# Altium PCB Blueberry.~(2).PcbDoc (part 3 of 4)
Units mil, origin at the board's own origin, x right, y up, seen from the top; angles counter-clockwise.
Board outline 2559.06 x 2204.72 mil, 6 copper layers (Top Layer, Mid-Layer 1, Mid-Layer 2, Mid-Layer 3, Mid-Layer 4, Bottom Layer); 211 components, 214 nets, 1171 pads, 598 vias.
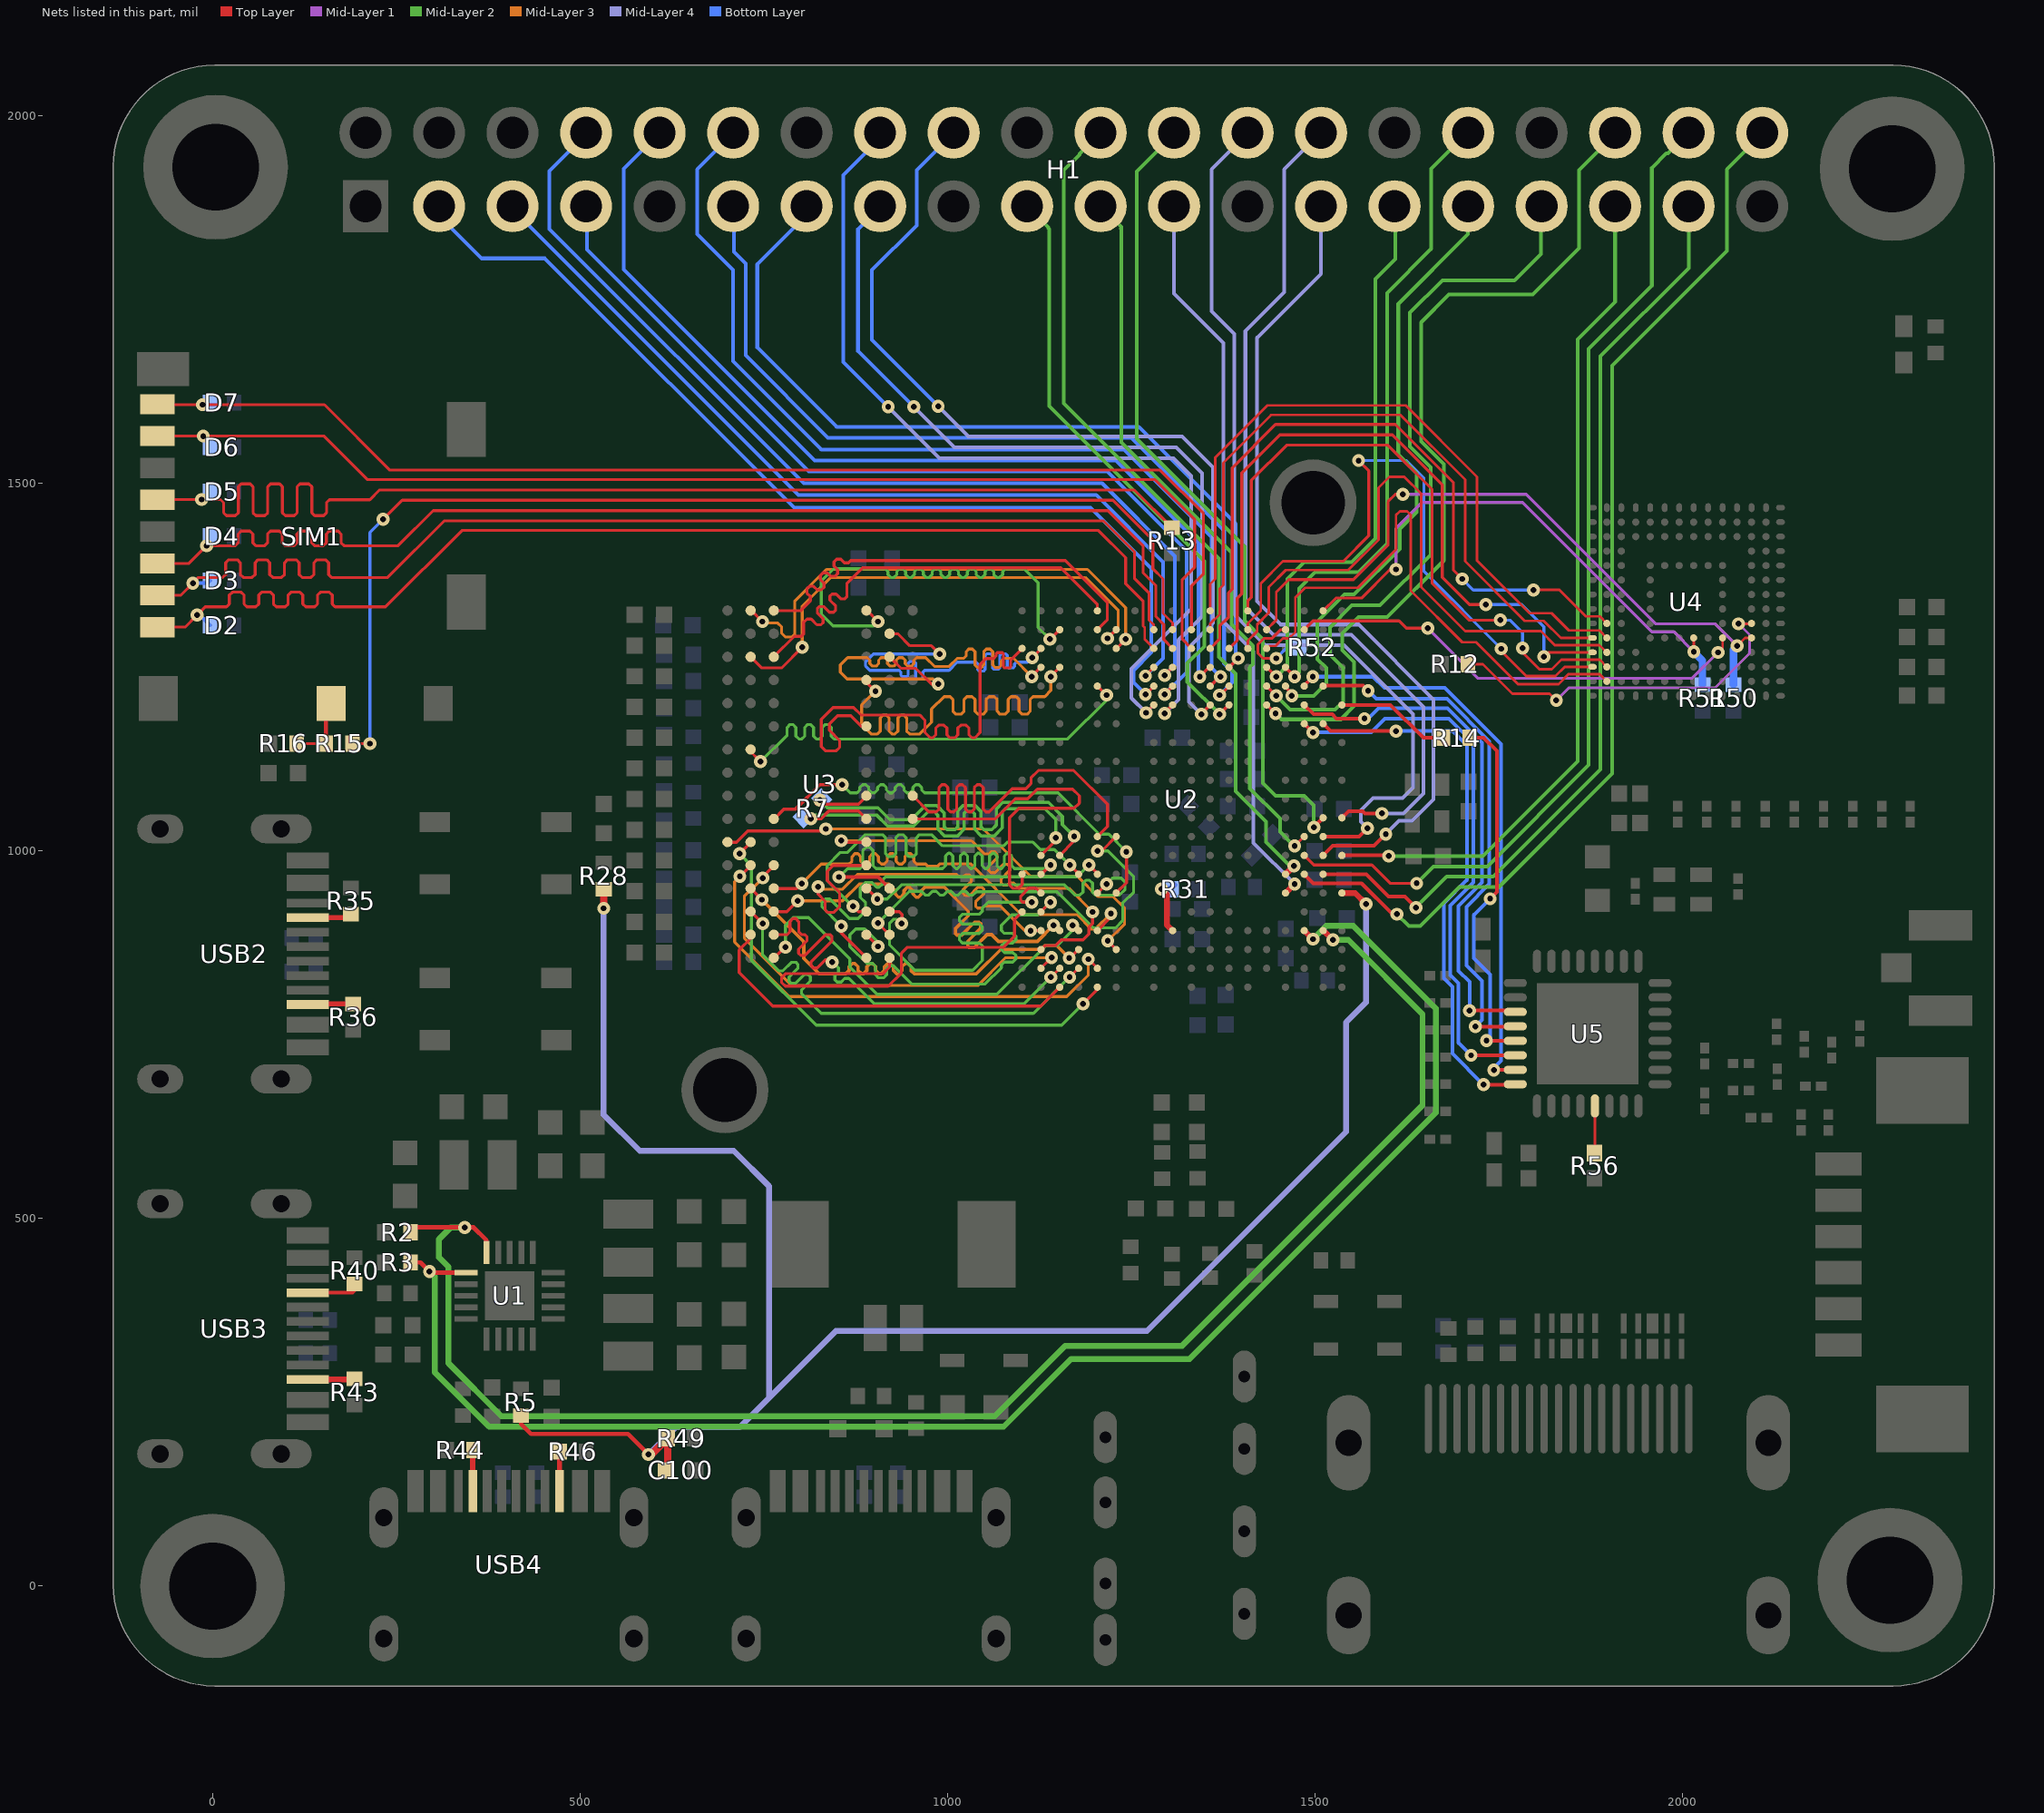
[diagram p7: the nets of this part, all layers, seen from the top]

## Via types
v1: diameter 17.7, hole 7.9, Top Layer to Bottom Layer, 439 vias
v2: diameter 18, hole 8, Top Layer to Bottom Layer, 138 vias
v3: diameter 24, hole 15, Top Layer to Bottom Layer, 19 vias
v4: diameter 24, hole 12, Top Layer to Bottom Layer, 2 vias

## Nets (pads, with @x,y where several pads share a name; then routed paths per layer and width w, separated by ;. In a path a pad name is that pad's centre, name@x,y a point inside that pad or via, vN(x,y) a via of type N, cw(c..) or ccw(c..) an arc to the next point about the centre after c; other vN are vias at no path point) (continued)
NetR14_2: R14.2 U2.A6 | length 156.2
  Top Layer w5: U2.A6@1536.29,1198.63 1602.37,1198.63 1647,1154 R14.2@1674,1154
NetR15_2: R15.2 R16.2 SIM1.11 | length 97.7
  Top Layer w4: R16.2@114,1146 R15.2@154,1146
  Top Layer w6: R15.2@154,1146 154,1193.65 SIM1.11@161.09,1200.74
NetR31_2: R31.2 U2.K18 | length 82.1
  Top Layer w8: v1(1291,948) 1298,941 1298,899.51 U2.K18@1305.97,891.55
  Bottom Layer w8: v1(1291,948) 1301.99,948 R31.2@1308,954
NetR35_2: R35.2 USB2.A5 | length 60.7
  Top Layer w7: USB2.A5@129.3,909.2 183.2,909.2 R35.2@188,914
NetR36_1: R36.1 USB2.B5 | length 62.1
  Top Layer w7: USB2.B5@129.3,791.1 130.2,792 R36.1@191,792
NetR40_2: R40.2 USB3.A5 | length 67.7
  Top Layer w5: USB3.A5@129.3,399.2 190.2,399.2 R40.2@195,404
NetR43_1: R43.1 USB3.B5 | length 64.1
  Top Layer w8: USB3.B5@129.3,281.1 186.09,281.1 186.99,282 R43.1@193,282
NetR44_2: R44.2 USB4.A5 | length 54.4
  Top Layer w7: R44.2@352,183 353.8,181.2 USB4.A5@353.8,129.3
NetR46_1: R46.1 USB4.B5 | length 53.7
  Top Layer w7: USB4.B5@471.9,129.3 472,129.4 R46.1@472,183
NetR52_1: R52.1 U2.D2 | length 122.9
  Top Layer w4: v1(1447,1262) 1429,1262 1422,1269 1422,1281 1430,1289 1441,1289 1452.99,1300.99 U2.D2@1459.52,1300.99
  Bottom Layer w4: v1(1447,1262) 1462,1277 R52.1@1478,1277
NetR56_1: R56.1 U5.29 | length 64.3
  Top Layer w4: R56.1@1880,589.04 1880.5,589.54 U5.29@1880.5,653.11
PH0: H1.23 U2.D16 | length 1007.5
  Top Layer w8: U2.D16@1459.52,942.73 1471.79,955 v1(1472,955)
  Mid-Layer 4 w5: H1.23@1308,1877 1308,1758 1375,1691 1375,1312 1416,1271 1416,1011 v1(1472,955)
PH1: H1.22 U2.D15 | length 1167.4
  Top Layer w8: U2.D15@1459.52,968.32 v1(1471,979.8) v1@1471,980
  Mid-Layer 2 w5: H1.22@1208,1977 1179.19,1948.19 1179.19,1947.19 1158,1926 1158,1609 1369,1398 1369,1264 1392,1241 1392,1081 1433,1040 1433,1012 1465.2,979.8 v1(1471,979.8)
PH2: H1.37 U2.B15 | length 1289.7
  Top Layer w5: U2.B15@1510.7,968.32 1569.68,968.32 1600,938 1622,938 v1(1637,923)
  Mid-Layer 2 w5: v1(1637,923) 1679,965 1742,965 1888,1111 1888,1673 2008,1793 H1.37@2008,1877
PH3: H1.40 U2.C15 | length 1490.6
  Top Layer w5: U2.C15@1485.11,968.32 1497.42,956 1563,956 1605,914 v1(1611,914)
  Mid-Layer 2 w5: v1(1611,914) 1627.35,897.65 1642.65,897.65 1696,951 1750,951 1904,1105 1904,1660 2060,1816 2060,1927 2108,1975 H1.40@2108,1977
PH4: H1.35 U2.A14 | length 1150.6
  Top Layer w5: U2.A14@1536.29,993.91 1599.09,993.91 v1(1600,993)
  Mid-Layer 2 w5: v1(1600,993) 1728,993 1857,1122 1857,1696 1908,1747 H1.35@1908,1877
PH5: H1.27 U2.B14 | length 1186.4
  Top Layer w5: U2.B14@1510.7,993.91 1523.79,1007 1580,1007 v1(1596,1023)
  Mid-Layer 4 w5: H1.27@1508,1877 1508,1785 1421,1698 1421,1340 1453,1308 1559,1308 1661,1206 1661,1070 1632,1041 1614,1041 v1(1596,1023)
PH6: H1.38 U2.C14 | length 1386.8
  Top Layer w4: U2.C14@1485.11,993.91 1498.01,981 1577,981 1602,956 v1(1638,956)
  Mid-Layer 2 w5: v1(1638,956) 1661,979 1734,979 1872,1117 1872,1683 1958,1769 1958,1929 1977.71,1948.71 1979.71,1948.71 H1.38@2008,1977
PH7: H1.24 U2.B12 | length 1107.1
  Top Layer w5: v1(1498,1032) 1498,1032.39 U2.B12@1510.7,1045.09
  Mid-Layer 2 w5: H1.24@1308,1977 1308,1975 1257,1924 1257,1561 1404,1414 1404,1313 1429,1288 1429,1092 1446,1075 1485,1075 1498,1062 v1(1498,1032)
PH8: H1.21 U2.C13 | length 1001.9
  Top Layer w4: v1(1472,1007) 1484.5,1019.5 U2.C13@1485.11,1019.5
  Mid-Layer 2 w5: H1.21@1208,1877 1236,1849 1236,1846 ; 1235.77,1846.23 1236,1846 ; v1(1472,1007) 1471,1007 1452,1026 1452,1044 1411,1085 1411,1250 1415,1254 1415,1279 1386,1308 1386,1406 1236,1556 1236,1846
PH9: H1.28 U2.A12 | length 1230.8
  Top Layer w5: U2.A12@1536.29,1045.09 1545.2,1054 1564.75,1054 1567.72,1051.03 v1(1590.7,1051.03)
  Mid-Layer 4 w5: H1.28@1508,1977 1458,1927 1458,1760 1405,1707 1405,1332 1443,1294 1549,1294 1647,1196 1647,1078 1620.03,1051.03 v1(1590.7,1051.03)
PH10: H1.26 U2.B13 | length 1264.1
  Top Layer w5: U2.B13@1510.7,1019.5 1559.5,1019.5 v1(1571,1031)
  Mid-Layer 4 w5: H1.26@1408,1977 1408,1976 1359,1927 1359,1734 1390,1703 1390,1322 1432,1280 1539,1280 1633,1186 1633,1086 1619,1072 1579,1072 1562,1055 1562,1040 v1(1571,1031)
PI0: H1.18 U2.H6 | length 1238
  Top Layer w4.5: v1(1345,1186) 1345,1186.47 U2.H6@1357.16,1198.63
  Mid-Layer 4 w5: v1(987,1605) 1028,1564 1319,1564 1361,1522 1361,1310 1328,1277 1328,1203 v1(1345,1186)
  Bottom Layer w5: v1(987,1605) 897,1695 897,1790 958,1851 958,1926 1008,1976 H1.18@1008,1977
PI1: H1.32 U2.D4 | length 890.9
  Top Layer w4.5: U2.D4@1459.52,1249.81 1459.52,1249.48 v1(1472,1237)
  Mid-Layer 2 w5: v1(1472,1237) 1478,1243 1478,1357 1500,1379 1559,1379 1598,1418 1598,1759 1658,1819 1658,1928 1707,1977 H1.32@1708,1977
PI2: H1.19 U2.G6 | length 836.6
  Top Layer w4.5: v1(1370,1186) 1382.63,1198.63 U2.G6@1382.75,1198.63
  Mid-Layer 2 w5: H1.19@1108,1877 1136.81,1848.19 1136.81,1847.19 1138,1846 1138,1605 1349,1394 1349,1278 1326,1255 1326,1230 v1(1370,1186)
PI3: H1.29 U2.E4 | length 764
  Top Layer w4.5: U2.E4@1433.93,1249.81 1434.19,1249.81 v1(1447,1237)
  Mid-Layer 2 w5: v1(1447,1237) 1462,1252 1462,1370 1485,1393 1550,1393 1582,1425 1582,1778 1609,1805 1609,1876 H1.29@1608,1877
PI4: H1.11 U2.G5 | length 1214.4
  Top Layer w4.5: v1(1370,1212) 1370.53,1212 U2.G5@1382.75,1224.22
  Bottom Layer w5: H1.11@707,1878 709,1876 709,1815 725,1799 725,1674 837,1562 1250,1562 1376,1436 1376,1255 1387,1244 1387,1229 v1(1370,1212)
PI5: H1.10 U2.H4 | length 1344.7
  Top Layer w4.5: v1(1343,1237) 1355.81,1249.81 U2.H4@1357.16,1249.81
  Bottom Layer w5: H1.10@608,1977 559,1928 559,1791 819,1531 1229,1531 1341,1419 1341,1239 v1(1343,1237)
PI6: H1.12 U2.H5 | length 1315.7
  Top Layer w4.5: U2.H5@1357.16,1224.22 1369.94,1237 v1(1371,1237)
  Bottom Layer w5: H1.12@708,1977 708,1976 659,1927 659,1839 708,1790 708,1666 828,1546 1240,1546 1359,1427 1359,1249 v1(1371,1237)
PI7: H1.13 U2.G4 | length 1171.7
  Top Layer w4.5: U2.G4@1382.75,1249.75 v1(1395,1262)
  Bottom Layer w5: H1.13@808,1877 808,1865 741,1798 741,1685 849,1577 1260,1577 1392,1445 1392,1265 v1(1395,1262)
PI8: H1.36 U2.E6 | length 1190.3
  Top Layer w4.5: U2.E6@1433.93,1198.63 1445.55,1187 v1(1446,1187)
  Mid-Layer 2 w5: v1(1446,1187) 1454,1179 1535,1179 1553,1197 1553,1257 1537,1273 1537,1296 1559,1318 1598,1318 1675,1395 1675,1526 1644,1557 1644,1719 1682,1757 1796,1757 1859,1820 1859,1926 1908,1975 H1.36@1908,1977
PI9: H1.31 U2.D5 | length 837.9
  Top Layer w4.5: U2.D5@1459.52,1224.22 1459.52,1222.73 1468.2,1214.05 v1(1468.2,1211)
  Mid-Layer 2 w5: v1(1468.2,1211) 1498,1211 1515,1228 1515,1249 1503,1261 1503,1312 1540,1349 1553,1349 1615,1411 1615,1438 1638,1461 1638,1514 1613,1539 1613,1744 1708,1839 H1.31@1708,1877
PI10: H1.3 U2.L5 | length 1384.7
  Top Layer w4: v1(1269,1213) 1269.16,1213 U2.L5@1280.38,1224.22
  Bottom Layer w5: H1.3@308,1877 308,1864 366,1806 452,1806 791,1467 1194,1467 1277,1384 1277,1270 1252.65,1245.65 1252.65,1229.35 v1(1269,1213)
PI11: H1.8 U2.K4 | length 1370.3
  Top Layer w4.5: v1(1295,1239) 1295.16,1239 U2.K4@1305.97,1249.81
  Bottom Layer w5: H1.8@508,1977 508,1975 458,1925 458,1846 804,1500 1210,1500 1309,1401 1309,1253 v1(1295,1239)
PI12: H1.7 U2.K5 | length 1268.4
  Top Layer w4.5: v1(1295,1213) 1295,1213.25 U2.K5@1305.97,1224.22
  Bottom Layer w5: H1.7@508,1877 509,1876 509,1818 811,1516 1217,1516 1325,1408 1325,1243 v1(1295,1213)
PI13: H1.33 U2.E5 | length 1025.7
  Top Layer w4.5: U2.E5@1433.93,1224.22 1447,1211.14 v1(1447,1211)
  Mid-Layer 2 w5: v1(1447,1211) 1466,1192 1527,1192 1538,1203 1538,1249 1520,1267 1520,1304 1550,1334 1588,1334 1657,1403 1657,1522 1629,1550 1629,1732 1673,1776 1771,1776 1807,1812 1807,1876 H1.33@1808,1877
PI14: H1.16 U2.L6 | length 1248.7
  Top Layer w4.5: v1(1270,1188) 1270,1188.25 U2.L6@1280.38,1198.63
  Mid-Layer 4 w5: v1(919,1604) 989,1534 1307,1534 1331,1510 1331,1329 1250,1248 1250,1208 v1(1270,1188)
  Bottom Layer w5: H1.16@908,1977 908,1969 858,1919 858,1665 v1(919,1604)
PI15: H1.5 U2.L4 | length 1269.3
  Top Layer w4: v1(1269,1238) 1269,1238.43 U2.L4@1280.38,1249.81
  Bottom Layer w5: H1.5@408,1877 408,1873 797,1484 1202,1484 1293,1393 1293,1262 v1(1269,1238)
PI16: H1.15 U2.K6 | length 1110.5
  Top Layer w4.5: v1(1295,1187) 1295,1187.66 U2.K6@1305.97,1198.63
  Mid-Layer 4 w5: v1(954,1604) 1009,1549 1311,1549 1346,1514 1346,1319 1314,1287 1314,1206 v1(1295,1187)
  Bottom Layer w5: H1.15@908,1877 908,1876 878,1846 878,1680 v1(954,1604)
PMU_SCK: R3.2 U1.6 U2.C18 | length 2170.3
  Top Layer w6: R3.2@269.44,440.28 282.72,440.28 v1(295,428) 296.58,426.42 U1.6@345.02,426.42
  Top Layer w8: U2.C18@1485.11,891.55 1496.65,880 v1(1497,880)
  Mid-Layer 2 w8: v1(295,428) 302,421 302,291 376,217 1076,217 1168,309 1329,309 1664,644 1664,786 1552,898 1515,898 v1(1497,880)
PMU_SDA: R2.2 U1.5 U2.B18 | length 2181.8
  Top Layer w6: R2.2@269.44,481.28 276.16,488 v1(342.84,488) 355,488 372.62,470.38 U1.5@372.62,454.02
  Top Layer w8: U2.B18@1510.7,891.55 1511.45,891.55 v1(1524,879)
  Mid-Layer 2 w8: v1(342.84,488) 324,488 308,472 308,447 321,434 321,303 393,231 1064,231 1160,327 1319,327 1646,654 1646,778 1545,879 v1(1524,879)
RESET: C100.2 R5.1 R28.1 R49.1 U2.A16 | length 2633.3
  Top Layer w6: R5.1@419.44,232.28 419.44,220.56 433,207 565,207 v1(593,179)
  Top Layer w8: U2.A16@1536.29,942.73 1554.27,942.73 v1(1569,928)
  Top Layer w10: v1(532,922) R28.1@532,948 ; v1(593,179) 597,179 R49.1@619,201 619,159.56 C100.2@616.8,157.36
  Mid-Layer 4 w8: v1(532,922) 532,641 581,592 709,592 756.85,544.15 756.85,255.85 ; v1(593,179) 630,216 717,216 756.85,255.85 ; v1(1569,928) 1569,794 1542,767 1542,618 1271,347 848,347 756.85,255.85
SA0: U2.P18 U3.N3 | length 627.4
  Top Layer w4: U3.N3@763.71,948.73 794.46,948.73 v1(801.27,955.53) ; U2.P18@1203.67,891.65 1222,909.98 v1(1222,915)
  Mid-Layer 3 w4: v1(801.27,955.53) 827.73,982 865.74,982 869.74,986 869.74,992.22 873.74,996.22 877.74,996.22 881.74,992.22 881.74,986 885.74,982 889.74,982 893.74,986 893.74,992.22 897.74,996.22 901.74,996.22 905.74,992.22 905.74,986 909.74,982 913.74,982 917.74,986 917.74,992.22 921.74,996.22 925.74,996.22 929.74,992.22 929.74,986 933.74,982 937.74,982 941.74,986 941.74,992.22 945.74,996.22 949.74,996.22 953.74,992.22 953.74,986 957.74,982 970,982 973,979 986,979 989.53,982.53 1030.95,982.53 1100.13,913.35 1175.94,913.35 1195.29,894 1201,894 v1(1222,915)
  other v1: 1222,915
SA1: U2.R15 U3.P7 | length 578.5
  Top Layer w4: v1(871.27,924.53) 878.57,917.23 U3.P7@889.69,917.23 ; v1(1166,981) 1178.08,968.92 U2.R15@1178.08,968.42
  Mid-Layer 2 w4: v1(871.27,924.53) 870.47,924.53 836,959 836,980 854,998 864,998 888,1022 911.36,1022 915.36,1018 915.36,996.22 919.36,992.22 925.36,992.22 929.36,996.22 929.36,1018 933.36,1022 939.36,1022 943.36,1018 943.36,996.22 947.36,992.22 953.36,992.22 957.36,996.22 957.36,1018 961.36,1022 978,1022 993,1007 1076,1007 1081,1012 1116,1012 1126,1002 1145,1002 v1(1166,981)
  other v1: 1166,981
SA2: U2.T18 U3.P3 | length 595.5
  Top Layer w4.5: U3.P3@763.71,917.23 781.23,917.23 v1(796,932) ; v1(1144,899) 1151.35,891.65 U2.T18@1152.49,891.65
  Mid-Layer 3 w4.5: v1(796,932) 856.73,932 879.73,955 919.58,955 928.55,946.03 928.55,941.63 933.05,937.13 936.05,937.13 940.55,941.63 940.55,946.03 945.05,950.53 948.05,950.53 952.55,946.03 952.55,941.63 957.05,937.13 960.05,937.13 964.55,941.63 964.55,946.03 969.05,950.53 995.47,950.53 1027.99,918.01 1027.99,911.65 1010.45,894.11 1010.45,887.74 1012.57,885.62 1018.94,885.62 1036.48,903.16 1042.84,903.16 1044.96,901.04 1044.96,894.68 1027.42,877.13 1027.42,870.77 1029.54,868.65 1035.91,868.65 1053.45,886.19 1059.81,886.19 1069,877 1122,877 v1(1144,899)
SA3: U2.R19 U3.N2 | length 605.8
  Top Layer w4.5: U3.N2@732.21,948.73 v1(747.27,933.67) ; v1@1164.27,854.22 1166.24,854.22 U2.R19@1178.08,866.06
  Mid-Layer 3 w4.5: v1(747.27,933.67) 804.27,876.67 804.27,853.73 825,833 861.47,833 865.97,837.5 865.97,842.5 870.47,847 873.47,847 877.97,842.5 877.97,837.5 882.47,833 885.47,833 889.97,837.5 889.97,842.5 894.47,847 897.47,847 901.97,842.5 901.97,837.5 906.47,833 909.47,833 913.97,837.5 913.97,842.5 918.47,847 921.47,847 925.97,842.5 925.97,837.5 930.47,833 933.47,833 937.97,837.5 937.97,842.5 942.47,847 945.47,847 949.97,842.5 949.97,837.5 954.47,833 1039,833 1072.22,866.22 1127.22,866.22 1132.22,871.22 1148.25,871.22 v1(1165.25,854.22)
  other v1: 1165.25,854.22
SA4: U2.U16 U3.P8 | length 530.8
  Top Layer w4: U3.P8@921.19,917.23 934.07,917.23 937.77,913.53 937.77,901.78 v1(937.2,901.22) ; v1(1114.29,930.22) 1101.58,930.22 1099.27,932.53 1099.27,938.53 1110.27,949.53 1118.52,949.53 1119.12,948.93 1120.79,948.93 U2.U16@1126.9,942.83
  Mid-Layer 2 w4: v1(937.2,901.22) 931.42,907 926,907 921,902 921,872 955.13,837.87 1033.87,837.87 1047,851 1047,870.79 1043,874.79 1019.99,874.79 1015.99,878.79 1015.99,883.79 1019.99,887.79 1043,887.79 1047,891.79 1047,896.79 1043,900.79 1019.99,900.79 1015.99,904.79 1015.99,909.79 1019.99,913.79 1043,913.79 1047,917.79 1047,922 1055.22,930.22 v1(1114.29,930.22)
SA5: U2.R20 U3.P2 | length 633.7
  Top Layer w4: U3.P2@732.21,917.23 v1(748.23,901.22) ; v1(1165.83,828.22) U2.R20@1178.08,840.47
  Mid-Layer 2 w4: v1(748.23,901.22) 748.23,858.77 770.16,836.84 775.82,836.84 787.66,848.68 793.32,848.68 796.15,845.85 796.15,840.19 784.31,828.35 784.31,822.69 787.13,819.87 792.79,819.87 804.63,831.71 810.29,831.71 813.12,828.88 813.12,823.22 801.28,811.38 801.28,805.72 828,779 1116.61,779 v1(1165.83,828.22)
  other v1: 1165.83,828.22
SA6: U2.N13 U3.R8 | length 577.7
  Top Layer w4: v1(905,902) 905,901.58 920.84,885.74 U3.R8@921.19,885.74 ; v1(1204,1000) 1209.66,1000 U2.N13@1229.26,1019.6
  Mid-Layer 2 w4: v1(905,902) 948,945 964.4,945 969.4,940 974.4,940 979.4,945 984.4,945 989.4,940 994.4,940 999.4,945 1004.4,945 1009.4,940 1014.4,940 1019.4,945 1024.4,945 1029.4,940 1034.4,940 1038.97,944.57 1149.14,944.57 1198.25,895.46 1228.46,895.46 1238,905 1238,929 1253,944 1253,965 1218,1000 v1(1204,1000)
SA7: U2.T21 U3.R2 | length 523.5
  Top Layer w4: U3.R2@732.21,885.74 732.21,881.21 716.27,865.27 716.27,834.73 762,789 1126.62,789 U2.T21@1152.49,814.87
SA8: U2.V17 U3.T8 | length 572.8
  Top Layer w4: U3.T8@920.87,854.58 920.87,841.87 912,833 779,833 774,828 774,821 779,816 919,816 937,834 937,861 945,869 1076,869 1091,884 1091,906.89 U2.V17@1101.25,917.14
SA9: U2.T20 U3.R3 | length 628.2
  Top Layer w4: U3.R3@763.37,886.08 781.37,886.08 785.37,890.08 785.37,904 789.37,908 793.37,908 797.37,904 797.37,890.08 801.37,886.08 805.92,886.08 808.59,883.41 808.59,877.75 797.25,866.41 797.25,860.75 800.07,857.93 805.73,857.93 834.07,886.27 839.73,886.27 842.56,883.44 842.56,877.78 814.22,849.44 814.22,843.78 817.05,840.95 822.7,840.95 834.05,852.3 839.7,852.3 v1(843,849) ; v1(1140.27,828.25) U2.T20@1152.49,840.47
  Mid-Layer 2 w4: v1(843,849) 851.31,840.69 851.31,835.03 846.55,830.27 846.55,824.61 849.38,821.78 855.04,821.78 859.8,826.54 865.46,826.54 900,792 1104.02,792 v1(1140.27,828.25)
SA10: U2.U19 U3.L7 | length 596.3
  Top Layer w4: v1(855,1014) 857.28,1011.72 U3.L7@889.69,1011.72 ; U2.U19@1126.9,866.06 1132.06,871.22 1146.27,871.22 1154.27,879.22 1184.27,879.22 1192.16,887.11 1192.16,896.41 1197,901.25 v1(1197,917)
  Mid-Layer 3 w4: v1(855,1014) 1032,1014 1050.05,995.95 1055.71,995.95 1058.54,998.78 1064.19,998.78 1067.02,995.95 1067.02,990.29 1055.71,978.98 1055.71,973.32 1058.54,970.49 1064.19,970.49 1075.51,981.81 1081.17,981.81 1083.99,978.98 1083.99,973.32 1072.68,962.01 1072.68,956.35 1075.51,953.52 1081.17,953.52 1083.99,956.35 1089.65,956.35 1096.78,949.22 1164.78,949.22 v1(1197,917)
  other v1: 1197,917
SA11: U2.U17 U3.R7 | length 570.5
  Top Layer w4: U3.R7@889.69,885.74 v1(905.27,870.16) ; U2.U17@1126.9,917.24 v1(1139.88,930.22)
  Mid-Layer 2 w4: v1(905.27,870.16) 905.27,875.73 887,894 875,894 867,886 867,870 890,847 897.86,847 901.86,843 901.86,831.46 905.86,827.46 912.86,827.46 916.86,831.46 916.86,839.86 921,844 926,844 951,819 1051,819 1073,841 1073,844.89 1077,848.89 1088.67,848.89 1092.67,852.89 1092.67,857.89 1088.67,861.89 1077,861.89 1073,865.89 1073,870.89 1077,874.89 1088.67,874.89 1092.67,878.89 1092.67,883.89 1088.67,887.89 1077,887.89 1073,891.89 1073,899 1087,913 1122.66,913 v1(1139.88,930.22)
  other v1: 1139.88,930.22 1139.88,930.22 1139.88,930.22 1139.88,930.22
SA12: U2.P16 U3.N7 | length 463.6
  Top Layer w4: U3.N7@889.69,948.73 890.07,948.73 v1(904.27,934.53) ; U2.P16@1203.67,942.83 1215.84,955 v1(1216,955)
  Mid-Layer 2 w4: v1(904.27,934.53) 917.53,934.53 937,954 1159,954 1173,940 1180.01,940 1184.01,944 1184.01,956.17 1188.01,960.17 1193.01,960.17 1197.01,956.17 1197.01,944 1201.01,940 1233.73,940 1241.27,947.53 1241.27,957.53 1235.8,963 1224,963 v1(1216,955)
SA13: U2.R18 U3.T3 | length 550.2
  Top Layer w4: U3.T3@763.71,854.24 778.68,869.22 v1(779.27,869.22) ; v1(1170,899) 1177.35,891.65 U2.R18@1178.08,891.65
  Mid-Layer 2 w4: v1(779.27,869.22) 779.27,898.88 789.77,909.38 810.62,909.38 867,853 867,842 904,805 1067,805 1133.22,871.22 1148.95,871.22 1170,892.27 v1(1170,899)
SA14: U2.P15 U3.T7 | length 561.8
  Top Layer w4.5: v1(855.27,897.53) 855.27,888.67 U3.T7@889.69,854.24 ; v1(1192,981) 1203.67,969.33 U2.P15@1203.67,968.42
  Mid-Layer 2 w4: v1(855.27,897.53) 829,923.8 829,930 833.53,934.53 839.47,934.53 866,908 878,908 888.27,918.27 888.27,929.53 881,936.8 881,950 888,957 897,957 903.47,950.53 906.69,950.53 911.19,955.03 911.19,960.5 915.69,965 1176,965 v1(1192,981)
SA15: U2.U18 U3.M7 | length 589
  Top Layer w4: v1(823.62,951.08) 823.62,941.18 833.27,931.53 833.27,919.53 836.27,916.53 845.53,916.53 853,924 853,943 836,960 836,972 844.23,980.23 U3.M7@889.69,980.23 ; v1(1112.84,891.65) U2.U18@1126.9,891.65
  Mid-Layer 3 w4: v1(823.62,951.08) 826.7,948 857,948 877.22,968.22 1011.78,968.22 1015.4,964.6 1021.06,964.6 1023.88,967.43 1029.54,967.43 1032.37,964.6 1032.37,958.94 1021.06,947.63 1021.06,941.97 1023.88,939.14 1029.54,939.14 1040.86,950.46 1046.51,950.46 1049.34,947.63 1049.34,941.97 1038.03,930.66 1038.03,925 1040.86,922.17 1046.51,922.17 1049.34,925 1072,925 1105.35,891.65 v1(1112.84,891.65)
SBA0: U2.P20 U3.M2 | length 676.1
  Top Layer w4: v1(717.27,965.28) U3.M2@732.21,980.23 ; v1(1191.27,852.87) U2.P20@1203.67,840.47
  Mid-Layer 3 w4: v1(717.27,965.28) 710.27,958.28 710.27,876.22 784.48,802 1162,802 1191.27,831.27 v1(1191.27,852.87)
SBA1: U2.U15 U3.N8 | length 599.6
  Top Layer w4.5: v1(852.27,964.53) 905.38,964.53 U3.N8@921.19,948.73 ; U2.U15@1126.84,968.32 1127.32,968.32 v1(1140,981)
  Mid-Layer 2 w4: v1(852.27,964.53) 863.73,976 880.4,976 884.4,980 884.4,1000.4 889,1005 894,1005 898.4,1000.6 898.4,980 902.4,976 993,976 997,980 997,993 1001,997 1003,997 1007,993 1007,980 1011,976 1013,976 1017,980 1017,993 1021,997 1023,997 1027,993 1027,980 1031,976 1033,976 1037,980 1037,993 1041,997 1043,997 1047,993 1047,980 1051,976 1053,976 1057,980 1057,993 1061,997 1063,997 1067,993 1067,980 1071,976 1073,976 1077,980 1077,993 1081,997 1083,997 1087,993 1087,980 1091,976 1135,976 v1(1140,981)
  other v1: 852.27,964.53
SBA2: U2.U20 U3.M3 | length 596.1
  Top Layer w4: v1(748.27,963.22) 748.27,964.78 U3.M3@763.71,980.23 ; U2.U20@1126.9,840.47 v1(1141.27,854.84)
  Mid-Layer 3 w4: v1(748.27,963.22) 723.27,938.22 723.27,881.73 788,817 1041.05,817 1078.89,854.84 v1(1141.27,854.84)
SCAS: U2.N16 U3.K3 | length 650.5
  Top Layer w4.5: U3.K3@763.71,1043.22 777.49,1057 793,1057 826.22,1090.22 v1(856.27,1090.22) ; U2.N16@1229.26,942.83 1243.27,956.84 1243.27,998.73 v1(1243,999)
  Mid-Layer 2 w4: v1(856.27,1090.22) 867.48,1079 876.53,1079 880.53,1083 880.53,1086.18 884.53,1090.18 888.53,1090.18 892.53,1086.18 892.53,1083 896.53,1079 900.53,1079 904.53,1083 904.53,1086.18 908.53,1090.18 912.53,1090.18 916.53,1086.18 916.53,1083 920.53,1079 924.53,1079 928.53,1083 928.53,1086.18 932.53,1090.18 936.53,1090.18 940.53,1086.18 940.53,1083 944.53,1079 948.53,1079 952.53,1083 952.53,1086.18 956.53,1090.18 960.53,1090.18 964.53,1086.18 964.53,1083 968.53,1079 1150,1079 1206,1023 1219,1023 v1(1243,999)
SCK_N: R7.2 U2.U14 U3.K7 | length 602.8
  Top Layer w4: U2.U14@1126.84,993.91 1147,1014.07 v1(1147,1018)
  Top Layer w4.4: v1(814,1044) 828,1044 838.27,1054.27 878.64,1054.27 U3.K7@889.69,1043.22
  Mid-Layer 2 w4.4: v1(814,1044) 819,1049 903.03,1049 917.89,1034.13 954.01,1034.13 973.48,1053.6 981.52,1053.6 986.6,1048.52 986.6,1029.52 995.52,1020.6 1013.48,1020.6 1022.4,1029.52 1022.4,1051.52 1024.48,1053.6 1033.52,1053.6 1036.6,1050.52 1036.6,1029.52 1045.52,1020.6 1063.48,1020.6 1074.4,1031.52 1074.4,1053.52 1078.48,1057.6 1132.4,1057.6 1147,1043 v1(1147,1018)
SCK_P: R7.1 U2.T14 U3.J7 | length 609.4
  Top Layer w4: U2.T14@1152.43,993.91 1172,1013.48 v1(1172,1020)
  Top Layer w4.4: v1(826,1069) 826,1067.56 822.11,1063.67 878.64,1063.67 U3.J7@889.69,1074.71
  Mid-Layer 2 w4.4: v1(826,1069) 836.27,1058.73 905.17,1058.73 921.37,1042.53 950.53,1042.53 970,1062 985,1062 995,1052 995,1033 999,1029 1010,1029 1014,1033 1014,1055 1021,1062 1037,1062 1045,1054 1045,1033 1049,1029 1060,1029 1066,1035 1066,1057 1075,1066 1137,1066 1156,1047 1156,1036 v1(1172,1020)
SCKE0: U2.V15 U3.K9 | length 489.9
  Top Layer w4: U3.K9@949.43,1043.46 1064.46,1043.46 1092,1071 1109,1071 1122,1084 1170,1084 1179,1075 1179,1065 1172,1058 1097,1058 1084,1045 1084,954 1089,949 1095.73,949 1101.31,954.57 U2.V15@1101.31,968.42
SCKE1: U2.P13 U3.J9 | length 566.3
  Top Layer w4: U3.J9@952.37,1075.08 974.44,1053 984.24,1053 988.18,1056.94 988.18,1086.24 992.12,1090.17 996.24,1090.17 1000.18,1086.24 1000.18,1056.94 1004.12,1053 1008.24,1053 1012.18,1056.94 1012.18,1086.24 1016.12,1090.17 1020.24,1090.17 1024.18,1086.24 1024.18,1056.94 1028.12,1053 1032.24,1053 1036.18,1056.94 1036.18,1086.24 1040.12,1090.17 1044.24,1090.17 1048.18,1086.24 1048.18,1056.94 1052.12,1053 1056.4,1053 1087.94,1084.53 1106.27,1084.53 1113.27,1091.53 1113.27,1099.53 1123.27,1109.53 1171.47,1109.53 1217.27,1063.73 1217.27,1033.2 U2.P13@1203.67,1019.6
SCS0: U2.P21 U3.L2 | length 704.3
  Top Layer w4.5: v1(716.71,996.22) U3.L2@732.21,1011.72 ; v1(1184,792) 1203.67,811.67 U2.P21@1203.67,814.82
  Mid-Layer 2 w4.3: v1(716.71,996.22) 732.67,980.26 732.67,851.33 821,763 1155,763 v1(1184,792)
SCS1: U2.N19 U3.L1 | length 662.6
  Top Layer w4: U3.L1@700.72,1011.72 712.46,1011.72 727.95,1027.22 831.22,1027.22 v1(834,1030) ; v1(1217.68,877.63) U2.N19@1229.26,866.06
  Mid-Layer 3 w4: v1(834,1030) 1048,1030 1112.78,965.22 1176.78,965.22 1204,938 1224.8,938 1240.65,922.15 1240.65,900.6 v1(1217.68,877.63)
SD_CLK: R14.1 U5.21 | length 501.8
  Top Layer w5: R14.1@1710,1154 1729,1154 1747,1136 1747,944 v1(1738,935) ; v1(1733,742) 1771.92,742 U5.21@1772.23,741.69
  Bottom Layer w5: v1(1733,742) 1738,747 1738,832.11 1716,854.11 1716,913 v1(1738,935)
SD_CMD: U2.C7 U5.22 | length 767.5
  Top Layer w4: U5.22@1780.24,722 U5.22@1781.23,722
  Top Layer w5: U2.C7@1485.11,1173.04 v1(1497,1161.14) v1@1497,1161 ; v1(1712,722) U5.22@1772.23,722.01
  Bottom Layer w5: v1(1497,1161.14) 1576.14,1161.14 1595,1180 1682.02,1180 1715,1147.02 1715,957.04 1683.5,925.54 1683.5,831.5 1695,820 1695,739 v1(1712,722)
SD_D0: U2.C6 U5.19 | length 721.4
  Top Layer w5: U2.C6@1485.11,1198.63 1497.73,1186 1523,1186 1529,1180 v1(1567,1180) ; v1(1710,783) 1770.29,783 U5.19@1772.23,781.06
  Bottom Layer w5: v1(1567,1180) 1572,1180 1586,1194 1680.04,1194 1727,1147.04 1727,957.02 1695,925.02 1695,837 1710,822 v1(1710,783)
SD_D1: U2.B5 U5.20 | length 725.8
  Top Layer w5: U2.B5@1510.7,1224.22 1511.48,1225 1565,1225 v1(1572,1218) ; v1(1718,761) 1771.85,761 U5.20@1772.23,761.38
  Bottom Layer w5: v1(1572,1218) 1583,1207 1679.06,1207 1737,1149.06 1737,955 1706,924 1706,844 1727,823 1727,770 v1(1718,761)
SD_D2: U2.C5 U5.23 | length 788.4
  Top Layer w5: U2.C5@1485.11,1224.22 1485.11,1224.76 1496.69,1236.34 v1(1496.69,1236.89) ; v1(1743,702) 1771.91,702 U5.23@1772.23,702.32
  Bottom Layer w5: v1(1496.69,1236.89) 1496.8,1237 1579,1237 1594,1222 1676.08,1222 1752.85,1145.23 1752.85,714.85 1743,705 v1(1743,702)
SD_D3: U2.B7 U5.24 | length 748.4
  Top Layer w5: U2.B7@1510.7,1173.04 1520.73,1163 v1(1610,1163) ; v1(1729,682) 1771.59,682 U5.24@1772.23,682.64
  Bottom Layer w5: v1(1610,1163) 1687,1163 1706.5,1143.5 1706.5,960.56 1675,929.06 1675,826.68 1686.5,815.18 1686.5,724.5 v1(1729,682)
SDC0_CLK: D5.2 R13.1 SIM1.5 | length 1673.4
  Top Layer w4: SIM1.5@-75.14,1477.7 -74.84,1478 v1(-15,1478) 10.58,1478 14.88,1473.7 14.88,1460 18.88,1456 30.88,1456 34.88,1460 34.88,1495.41 38.88,1499.41 50.88,1499.41 54.88,1495.41 54.88,1460 58.88,1456 70.88,1456 74.88,1460 74.88,1495.41 78.88,1499.41 90.88,1499.41 94.88,1495.41 94.88,1460 98.88,1456 110.88,1456 114.88,1460 114.88,1495.41 118.88,1499.41 130.88,1499.41 134.88,1495.41 134.88,1460 138.88,1456 150.88,1456 154.88,1460 154.88,1473.7 158.88,1477.7 213.7,1477.7 227,1491 1254,1491 R13.1@1305,1440
SDC0_CMD: D4.2 SIM1.3 U2.K3 | length 1669.5
  Top Layer w3.5: 1282,1362 1283,1361 1283,1319 1294,1308
  Top Layer w4: SIM1.3@-75.14,1391.09 -32.27,1391.09 v1(-8.23,1415.12) 30.64,1415.12 34.64,1419.12 34.64,1431.12 38.64,1435.12 50.64,1435.12 54.64,1431.12 54.64,1419.12 58.64,1415.12 70.64,1415.12 74.64,1419.12 74.64,1431.12 78.64,1435.12 90.64,1435.12 94.64,1431.12 94.64,1419.12 98.64,1415.12 110.64,1415.12 114.64,1419.12 114.64,1431.12 118.64,1435.12 130.64,1435.12 134.64,1431.12 134.64,1419.12 138.64,1415.12 150.64,1415.12 154.64,1419.12 154.64,1431.12 158.64,1435.12 170.64,1435.12 174.64,1431.12 174.64,1419.12 178.64,1415.12 252.12,1415.12 300,1463 1218,1463 1266,1415 1266,1378 1282,1362 ; 1294,1308 1294,1287.36 U2.K3@1305.97,1275.4
SDC0_D0: D6.2 SIM1.7 U2.J3 | length 1645.9
  Top Layer w4: SIM1.7@-75.14,1564.32 v1(-12.87,1564.32) 151.68,1564.32 211,1505 1282,1505 1336,1451 1336,1386 1319,1369 1319,1287.96 U2.J3@1331.57,1275.4
SDC0_D1: D7.2 SIM1.8 U2.J2 | length 1649.5
  Top Layer w4: SIM1.8@-75.14,1607.62 -74.51,1607 v1(-14,1607) 152,1607 241,1518 1289,1518 1348,1459 1348,1377 1331.57,1360.57 U2.J2@1331.57,1300.99
SDC0_D2: D2.2 SIM1.1 U2.L3 | length 1672.1
  Top Layer w3.5: 1265.5,1340 1266,1339.5 1266,1305.76 1268,1303.76 1268,1287.77 U2.L3@1280.38,1275.4
  Top Layer w4: SIM1.1@-75.14,1304.47 -37.53,1304.47 v1(-21,1321) -10,1332 18.68,1332 22.68,1336 22.68,1348 26.68,1352 38.68,1352 42.68,1348 42.68,1336 46.68,1332 58.68,1332 62.68,1336 62.68,1348 66.68,1352 78.68,1352 82.68,1348 82.68,1336 86.68,1332 98.68,1332 102.68,1336 102.68,1348 106.68,1352 118.68,1352 122.68,1348 122.68,1336 126.68,1332 138.68,1332 142.68,1336 142.68,1348 146.68,1352 158.68,1352 162.68,1348 162.68,1336 166.68,1332 235,1332 339,1436 1205,1436 1242,1399 1242,1363.5 1265.5,1340
  Bottom Layer w5: v1(-21,1321) -17.61,1321 D2.2@-3.61,1307
SDC0_D3: D3.2 SIM1.2 U2.L2 | length 1684.6
  Top Layer w3.5: 1273,1352 1274,1351 1274,1314 1280.38,1307.62 U2.L2@1280.38,1300.99
  Top Layer w4: SIM1.2@-75.14,1347.78 -43.51,1347.78 v1(-26.99,1364.31) -19.3,1372 13.69,1372 17.69,1376 17.69,1392 21.69,1396 33.69,1396 37.69,1392 37.69,1376 41.69,1372 53.69,1372 57.69,1376 57.69,1392 61.69,1396 73.69,1396 77.69,1392 77.69,1376 81.69,1372 93.69,1372 97.69,1376 97.69,1392 101.69,1396 113.69,1396 117.69,1392 117.69,1376 121.69,1372 133.69,1372 137.69,1376 137.69,1392 141.69,1396 153.69,1396 157.69,1392 157.69,1376 161.69,1372 238,1372 315,1449 1212,1449 1254,1407 1254,1371 1273,1352
  Bottom Layer w5: v1(-26.99,1364.31) -6.9,1364.31 D3.2@-3.61,1367.6
SDC0_DET: R15.1 U2.K2 | length 1549.8
  Top Layer w3.5: 1293,1370 1293,1323 1305.97,1310.03 U2.K2@1305.97,1300.99
  Top Layer w4: R15.1@190,1146 v1(214,1146) ; v1(232,1451) 258,1477 1225,1477 1279,1423 1279,1384 1293,1370
  Bottom Layer w4: v1(214,1146) 214,1433 v1(232,1451)
SDC2_CLK: R12.1 U4.M6 | length 493.8
  Top Layer w3.5: R12.1@1708,1254 1728,1254 1768,1214 1819,1214 v1(1828,1205) ; v1(2076,1309) 2093.11,1309 U4.M6@2093.59,1309.47
  Mid-Layer 1 w3.5: v1(1828,1205) 1845,1222 2044,1222 2091,1269 2091,1294 v1(2076,1309)
SDC2_CMD: R50.2 U2.E2 U4.M5 | length 937.5
  Top Layer w3.5: U2.E2@1433.93,1300.99 1447,1314.06 1447,1352 1464,1369 ; v1(2074,1279) 2084.78,1289.78 U4.M5@2093.59,1289.78
  Top Layer w4: 1464,1369 1552,1369 1599,1416 1599,1475 1609,1485 v1(1619,1485)
  Mid-Layer 1 w4: v1(1619,1485) 1787,1485 1963,1309 2044,1309 v1(2074,1279)
  Bottom Layer w10: R50.2@2069,1226 2069,1274 v1(2074,1279)
SDC2_D0: U2.F2 U4.A3 | length 872.8
  Top Layer w3.5: 1408.34,1309.34 1426,1327 1426,1364 1456,1394 ; v1(1753,1275) 1753,1272 1787,1238 1827,1238 1839.41,1250.41 U4.A3@1877.05,1250.41
  Top Layer w4: U2.F2@1408.34,1300.99 1408.34,1309.34 ; 1456,1394 1538,1394 1573,1429 1573,1517 v1(1559,1531)
  Bottom Layer w4: v1(1559,1531) 1624,1531 1648,1507 1648,1380 v1(1753,1275)
SDC2_D1: U2.G3 U4.A4 | length 969.8
  Top Layer w3.5: v1(1811,1264) 1817,1270 1876.94,1270 U4.A4@1877.05,1270.11
  Top Layer w4: U2.G3@1382.75,1275.4 1394,1286.65 1394,1344 1400,1350 1400,1514 1452,1566 1605,1566 1673,1498 1673,1372 1710,1335 v1(1732,1335)
  Bottom Layer w4: v1(1732,1335) 1781,1335 1811,1305 v1(1811,1264)
SDC2_D2: U2.H2 U4.A5 | length 954
  Top Layer w3.5: U2.H2@1357.16,1300.99 1357.16,1309.16 1370,1322 1370,1357 1375,1362 1375,1528 1440,1593 1616,1593 1704,1505 1704,1394 1785,1313 1811,1313 1834.22,1289.78 U4.A5@1877.05,1289.78
SDC2_D3: U2.E3 U4.B2 | length 762.4
  Top Layer w3.5: U2.E3@1433.93,1275.4 1437.53,1279 1446,1279 1456,1289 1464,1289 1473,1298 1473,1345 1486,1358 1558,1358 1610,1410 1610,1457 1615,1462 1625,1462 1630,1457 1630,1354 1700,1284 1719,1284 1776,1227 1831,1227 1844.46,1240.46 1887.01,1240.46 U4.B2@1896.73,1230.74
SDC2_D4: U2.F1 U4.B3 | length 909.4
  Top Layer w3.5: v1(1782,1276) 1782,1270 1805,1247 1822,1247 1835,1260 1887.15,1260 U4.B3@1896.73,1250.41
  Top Layer w4: U2.F1@1408.34,1326.59 1408.34,1340.34 1413,1345 1413,1504 1461,1552 1599,1552 1659,1492 1659,1364 1709,1314 v1(1752,1314)
  Bottom Layer w4: v1(1752,1314) 1765,1314 1782,1297 v1(1782,1276)
SDC2_D5: U2.F3 U4.B4 | length 832.3
  Top Layer w3.5: U2.F3@1408.34,1275.4 1408.34,1286.14 1421,1298.8 1421,1308 1437,1324 1437,1359 1460,1382 1545,1382 1586,1423 1586,1494 1601,1509 1621,1509 1644,1486 1644,1359 1704,1299 1807,1299 1826,1280 1886.84,1280 U4.B4@1896.73,1270.11
SDC2_D6: U2.H1 U4.B5 | length 971.2
  Top Layer w3.5: U2.H1@1357.16,1326.59 1357.16,1363.16 1364,1370 1364,1535 1435,1606 1623,1606 1720,1509 1720,1395 1791.5,1323.5 1821.5,1323.5 1845,1300 1886.52,1300 U4.B5@1896.73,1289.78
SDC2_D7: U2.H3 U4.B6 | length 973.9
  Top Layer w3.5: v1(1797,1355) 1832,1355 1868,1319 1887.21,1319 U4.B6@1896.73,1309.47
  Top Layer w4: U2.H3@1357.16,1275.4 1370,1288.24 1370,1306 1382,1318 1382,1351 1387,1356 1387,1521 1446,1580 1609,1580 1688,1501 1688,1382 v1(1700,1370)
  Bottom Layer w4: v1(1700,1370) 1715,1355 v1(1797,1355)
SDC2_DS: R51.2 U2.B1 U4.H5 | length 751.1
  Top Layer w3.5: U4.H5@2014.85,1289.78 2015,1289.63 v1(2015,1271)
  Top Layer w4: U2.B1@1510.7,1326.59 1528.11,1344 1563,1344 1602,1383 v1(1610,1383)
  Mid-Layer 1 w4: v1(1610,1383) 1610,1439 1645,1474 1782,1474 1958,1298 1988,1298 v1(2015,1271)
  Bottom Layer w10: v1(2015,1271) 2027,1259 R51.2@2027,1226
SDC2_RST: U2.C2 U4.K5 | length 637
  Top Layer w3.5: v1(2048,1270) 2054.22,1276.22 U4.K5@2054.22,1289.78
  Top Layer w4: U2.C2@1485.11,1300.99 1497.12,1313 1614,1313 1624,1303 v1(1653,1303)
  Mid-Layer 1 w4: v1(1653,1303) 1721,1235 2013,1235 v1(2048,1270)
SDQ0: U2.N3 U3.A2 | length 676.8
  Top Layer w4: U3.A2@732.21,1326.68 733.32,1326.68 v1(748,1312) ; U2.N3@1229.26,1275.5 1229.5,1275.5 v1(1242,1288)
  Mid-Layer 3 w4: v1(748,1312) 750,1310 769,1310 774,1305 774,1296 779,1291 788,1291 792,1295 792,1340 835,1383 1190,1383 1242,1331 v1(1242,1288)
SDQ1: U2.U4 U3.C8 | length 657.5
  Top Layer w4: U3.C8@921.19,1263.69 936.42,1248.46 956.28,1248.46 977.75,1227 v1(987,1227) ; v1@1114.27,1237.28 U2.U4@1126.9,1249.91
  Mid-Layer 3 w4: v1(987,1227) 980,1234 863,1234 854,1243 854,1253 864,1263 890.53,1263 894.03,1259.5 894.03,1254.88 897.53,1251.38 902.53,1251.38 906.03,1254.88 906.03,1259.5 909.53,1263 914.53,1263 918.03,1259.5 918.03,1254.88 921.53,1251.38 926.53,1251.38 930.03,1254.88 930.03,1259.5 933.53,1263 938.53,1263 942.03,1259.5 942.03,1254.88 945.53,1251.38 950.53,1251.38 954.03,1254.88 954.03,1259.5 957.53,1263 970,1263 982,1251 1002,1251 1013,1262 1021.64,1262 1025.14,1265.5 1025.14,1271.02 1028.64,1274.52 1033.64,1274.52 1037.14,1271.02 1037.14,1252.98 1040.64,1249.48 1045.64,1249.48 1049.14,1252.98 1049.14,1271.02 1052.64,1274.52 1057.64,1274.52 1061.14,1271.02 1061.14,1252.98 1064.64,1249.48 1069.64,1249.48 1073.14,1252.98 1073.14,1258.5 1076.64,1262 1089.48,1262 v1(1114.27,1237.22)
  other v1: 1114.27,1237.22
SDQ2: U2.N2 U3.C2 | length 668.9
  Top Layer w4: U3.C2@732.21,1263.69 746.9,1249 774,1249 v1(802,1277) ; v1(1217.39,1289.22) U2.N2@1229.26,1301.09
  Mid-Layer 3 w4: v1(802,1277) 802,1333 841,1372 1187,1372 1232,1327 1232,1303.83 v1(1217.39,1289.22)
SDQ3: U2.T4 U3.D7 | length 647.1
  Top Layer w4: U3.D7@889.69,1232.19 889.69,1229.19 v1(901.7,1217.18) ; v1(1140.27,1237.22) 1140.27,1237.69 U2.T4@1152.49,1249.91
  Mid-Layer 3 w4: v1(901.7,1217.18) 883,1198.48 883,1172 896,1159 904.25,1159 908.25,1163 908.25,1181 912.25,1185 916.25,1185 920.25,1181 920.25,1163 924.25,1159 928.25,1159 932.25,1163 932.25,1181 936.25,1185 940.25,1185 944.25,1181 944.25,1163 948.25,1159 962,1159 978,1175 978,1193 995,1210 1003.19,1210 1007.19,1206 1007.19,1190 1011.19,1186 1018.19,1186 1022.19,1190 1022.19,1206 1026.19,1210 1033.19,1210 1037.19,1206 1037.19,1190 1041.19,1186 1048.19,1186 1052.19,1190 1052.19,1206 1056.19,1210 1063.19,1210 1067.19,1206 1067.19,1190 1071.19,1186 1078.19,1186 1082.19,1190 1082.19,1206 1086.19,1210 1093.19,1210 1097.19,1206 1097.19,1190 1101.19,1186 1108.19,1186 1112.19,1190 1112.19,1206 1116.19,1210 1132,1210 1140.27,1218.27 v1(1140.27,1237.22)
  other v1: 1140.27,1237.22 1140.27,1237.22 1140.27,1237.22
SDQ4: U2.U3 U3.B8 | length 588.5
  Top Layer w4: U3.B8@921.19,1295.19 932.61,1295.19 948.58,1279.22 977.78,1279.22 v1(989,1268) ; v1(1115,1263) 1126.9,1274.9 U2.U3@1126.9,1275.5
  Bottom Layer w4: v1(989,1268) 899.05,1268 888.27,1257.22 888.27,1251.38 894.11,1245.53 933.94,1245.53 936.28,1243.19 936.28,1239.1 938.28,1237.1 944.28,1237.1 946.28,1239.1 946.28,1255.53 948.28,1257.53 954.28,1257.53 956.28,1255.53 956.28,1235.53 958.28,1233.53 964.28,1233.53 966.28,1235.53 966.28,1243.19 968.63,1245.53 1001.77,1245.53 1012.86,1256.62 1038.58,1256.62 1040.92,1254.27 1040.92,1246.62 1042.92,1244.62 1048.92,1244.62 1050.92,1246.62 1050.92,1266.03 1052.92,1268.03 1058.92,1268.03 1060.92,1266.03 1060.92,1249.13 1062.92,1247.13 1068.92,1247.13 1070.92,1249.13 1070.92,1266.03 1072.92,1268.03 1078.92,1268.03 1080.92,1266.03 1080.92,1250.96 1082.92,1248.96 1088.92,1248.96 1090.92,1250.96 1090.92,1254.27 1093.27,1256.62 1108.62,1256.62 v1(1115,1263)
SDQ5: U2.P1 U3.C3 | length 602.6
  Top Layer w4: U3.C3@763.37,1264.08 791.29,1292 801,1292 804,1295 804,1311 808.52,1315.52 814.18,1315.52 822.02,1307.68 827.68,1307.68 830.51,1310.51 830.51,1316.17 822.67,1324.01 822.67,1329.67 825.5,1332.5 831.15,1332.5 839,1324.65 844.65,1324.65 847.48,1327.48 847.48,1333.14 839.64,1340.98 839.64,1346.64 842.47,1349.47 848.12,1349.47 854.59,1343 860,1343 863,1346 863,1364 884,1385 1154,1385 1203.61,1335.39 U2.P1@1203.61,1326.59
SDQ6: U2.T2 U3.A7 | length 668.6
  Top Layer w4: U3.A7@888.56,1326.93 890.07,1326.93 v1(905,1312) ; v1(1139,1288) 1139.4,1288 U2.T2@1152.49,1301.09
  Mid-Layer 2 w4: v1(905,1312) 899,1306 844,1306 828,1322 828,1367 845,1384 914.75,1384 918.75,1380 918.75,1376 922.75,1372 926.75,1372 930.75,1376 930.75,1380 934.75,1384 938.75,1384 942.75,1380 942.75,1376 946.75,1372 950.75,1372 954.75,1376 954.75,1380 958.75,1384 962.75,1384 966.75,1380 966.75,1376 970.75,1372 974.75,1372 978.75,1376 978.75,1380 982.75,1384 986.75,1384 990.75,1380 990.75,1376 994.75,1372 998.75,1372 1002.75,1376 1002.75,1380 1006.75,1384 1010.75,1384 1014.75,1380 1014.75,1376 1018.75,1372 1022.75,1372 1026.75,1376 1026.75,1380 1030.75,1384 1034.75,1384 1038.75,1380 1038.75,1376 1042.75,1372 1046.75,1372 1050.75,1376 1050.75,1380 1054.75,1384 1058.75,1384 1062.75,1380 1062.75,1376 1066.75,1372 1070.75,1372 1074.75,1376 1074.75,1380 1078.75,1384 1104,1384 1123,1365 1123,1304 v1(1139,1288)
SDQ7: U2.P2 U3.A3 | length 608.7
  Top Layer w4: U3.A3@763.71,1326.68 799.68,1326.68 813.33,1340.33 813.33,1345.98 808.48,1350.83 808.48,1356.48 812.02,1360.02 817.68,1360.02 822.52,1355.18 828.18,1355.18 831.71,1358.71 831.71,1364.37 826.87,1369.21 826.87,1374.87 830.4,1378.4 836.06,1378.4 840.9,1373.56 846.56,1373.56 850.1,1377.1 850.1,1382.75 845.25,1387.6 845.25,1393.25 848.79,1396.79 854.44,1396.79 859.29,1391.94 864.94,1391.94 868,1395 1160,1395 1217,1338 1217,1314.27 1215.27,1312.53 1215.11,1312.53 U2.P2@1203.67,1301.09
SDQ8: U2.P5 U3.G2 | length 642.7
  Top Layer w4: U3.G2@728.96,1137.95 v1(745.45,1121.46) ; U2.P5@1203.68,1224.32 v1(1216,1212)
  Mid-Layer 2 w4: v1(745.45,1121.46) 781.44,1157.45 781.44,1168 785.44,1172 789.44,1172 793.44,1168 793.44,1156.22 797.44,1152.22 801.44,1152.22 805.44,1156.22 805.44,1168 809.44,1172 813.44,1172 817.44,1168 817.44,1156.22 821.44,1152.22 825.44,1152.22 829.44,1156.22 829.44,1168 833.44,1172 837.44,1172 841.44,1168 841.44,1156.22 845.44,1152.22 1163.22,1152.22 1216,1205 v1(1216,1212)
  other v1: 1216,1212
SDQ9: U2.V3 U3.F7 | length 661.6
  Top Layer w4: U3.F7@889.37,1169.58 882.42,1169.58 868,1184 850,1184 839,1173 839,1164 853,1150 853,1141 848,1136 834,1136 828,1142 828,1179 844,1195 872,1195 882,1185 961.72,1185 969,1177.72 969,1161 976,1154 979.85,1154 983.85,1158 983.85,1167.22 987.85,1171.22 994.85,1171.22 998.85,1167.22 998.85,1158 1002.85,1154 1009.85,1154 1013.85,1158 1013.85,1167.22 1017.85,1171.22 1024.85,1171.22 1028.85,1167.22 1028.85,1158 1032.85,1154 1037,1154 1044,1161 1044,1253.45 1052.16,1261.61 1062.24,1261.61 1065.75,1265.13 1065.75,1268.34 1067.25,1269.84 1074.25,1269.84 1075.75,1268.34 1075.75,1250.46 1077.25,1248.96 1084.25,1248.96 1085.75,1250.46 1085.75,1259.75 U2.V3@1101.31,1275.31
